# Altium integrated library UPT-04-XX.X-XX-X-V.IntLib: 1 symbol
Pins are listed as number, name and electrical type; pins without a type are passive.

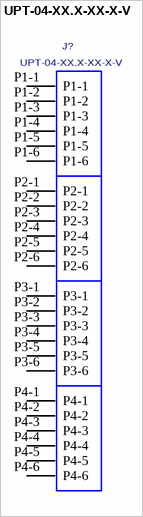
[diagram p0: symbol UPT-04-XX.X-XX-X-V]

## UPT-04-XX.X-XX-X-V
designator J?
UPT-V, ASSEMBLY.; MANUFACTURER: SAMTEC
footprint UPT-04-XX.X-XX-X-V
pins: P1-1, P1-2, P1-3, P1-4, P1-5, P1-6, P2-1, P2-2, P2-3, P2-4, P2-5, P2-6, P3-1, P3-2, P3-3, P3-4, P3-5, P3-6, P4-1, P4-2, P4-3, P4-4, P4-5, P4-6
